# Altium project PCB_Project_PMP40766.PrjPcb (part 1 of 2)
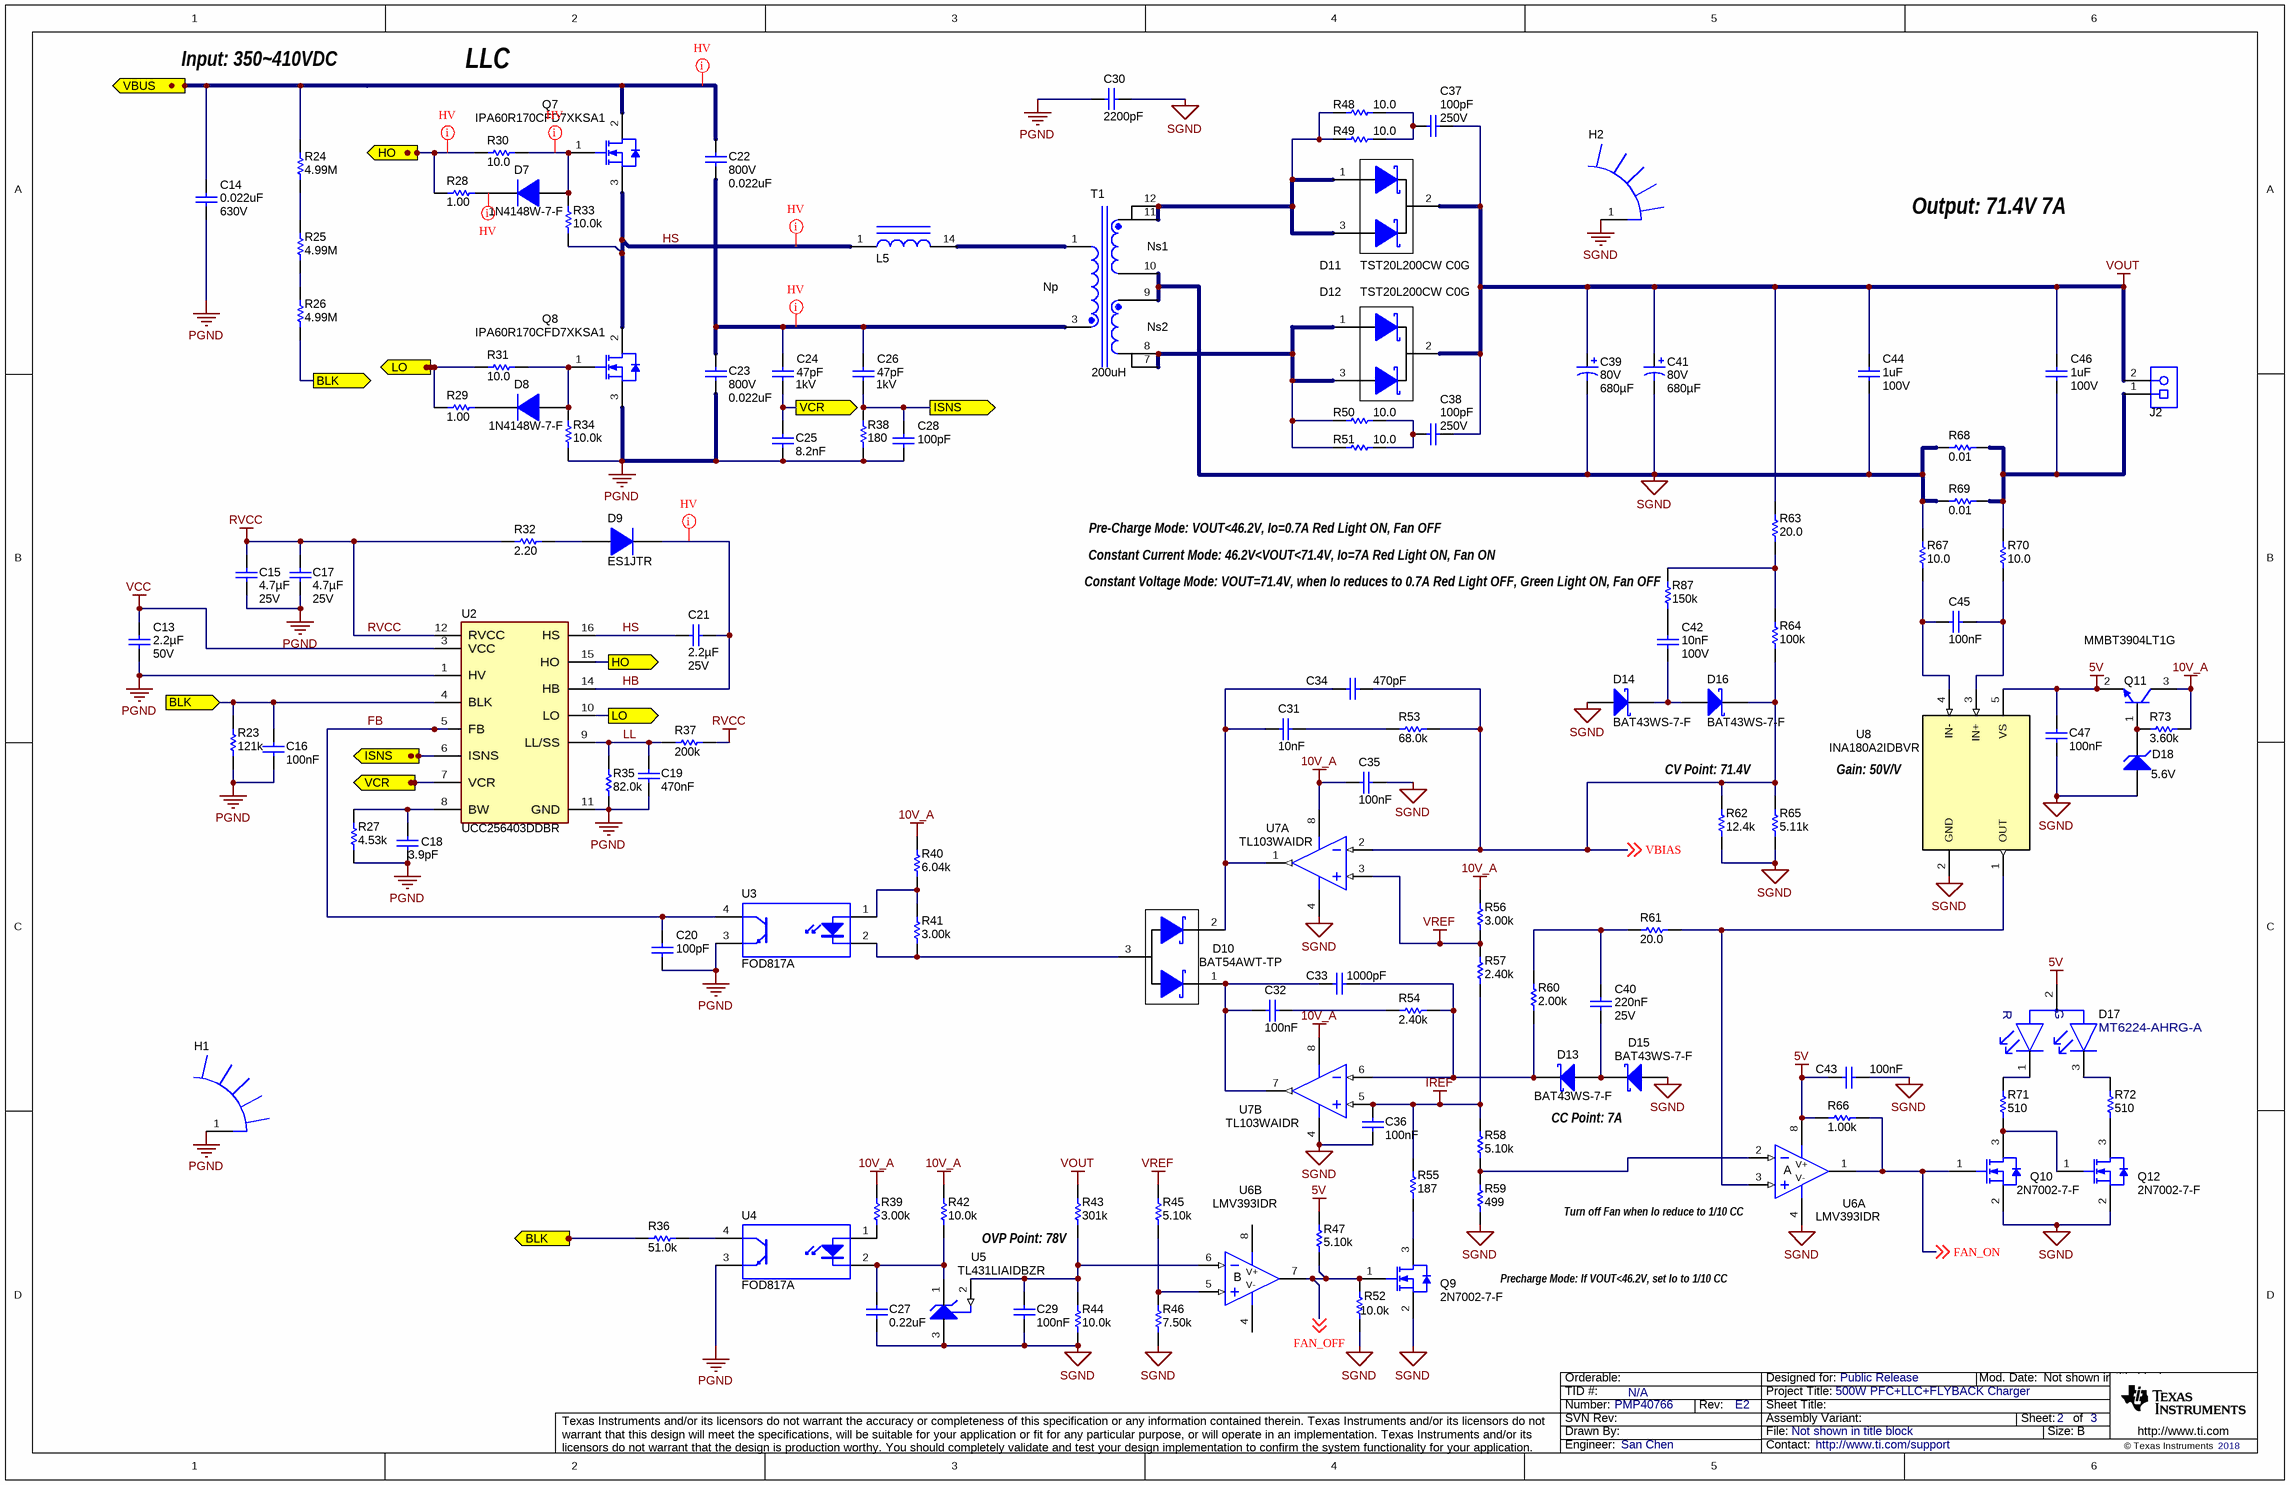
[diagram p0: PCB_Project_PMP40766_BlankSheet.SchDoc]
TID: N/A; TechSupport: http://www.ti.com/support; SCH_Rev: E2; PRJ_Title: 500W PFC+LLC+FLYBACK Charger; PRJ_Number: PMP40766; PRJ_Engineer: San Chen; PRJ_Customer: Public Release; PCB_Rev: E2; PCB_Layout: San Chen; CopyrightYear: 2018
3 sheets, 214 parts. Net scope: flat (ports and power ports of the same name join across sheets).
Board file: PCB_Project_PMP40766_PCB.PcbDoc
Sheets:
  PCB_Project_PMP40766_BlankSheet.SchDoc
  PCB_Project_PMP40766_CoverSheet.SchDoc
  PCB_Project_PMP40766_EVM_Hardware.SchDoc

## Sheet PCB_Project_PMP40766_BlankSheet.SchDoc
size 431 x 279 mm; Date: Not shown in title block; ApprovedBy: Not shown in title block; CheckedBy: Not shown in title block; Author: Not shown in title block; CompanyName: Not shown in title block; Engineer: Not shown in title block; Organization: Not shown in title block; Address1: Not shown in title block; Address2: Not shown in title block; Address3: Not shown in title block; Address4: Not shown in title block; DocumentNumber: 1; Revision: Use project parameter SCH_Rev; SheetNumber: 2; SheetTotal: 3; PageSetup: Record=PageOptions¦CenterHorizontal=True¦CenterVertical=True¦PrintScale=1.00¦XCorrection=1.00¦YCorrection=1.00¦PrintKind=0¦BorderSize=5000000¦LeftOffset=0¦BottomOffset=0¦Orientation=2¦PaperLength=1000¦PaperWidth=1000¦Scale=100¦PaperSource=15¦PrintQuality=600¦MediaType=1¦DitherType=10¦PaperKind=Letter¦PrintScaleMode=1

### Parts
C13  Cap_F: 2.2µF  VDC_V: 50V  [0805_HV]  (hidden comment: C2012X7R1H225K125AC)
C14  VDC_V: 630V  ValueDisplayed: 0.022uF  [ECWF_L_1250x620x1050]  (hidden comment: ECW-F6223HL)
C15  Cap_F: 4.7µF  VDC_V: 25V  [0805_HV]  (hidden comment: C2012X7R1E475K125AB)
C16  Cap_F: 100nF  [0603]  (hidden comment: C0603X104K3RACTU)
C17  Cap_F: 4.7µF  VDC_V: 25V  [0805_HV]  (hidden comment: C2012X7R1E475K125AB)
C18  ValueDisplayed: 3.9pF  [0603]  (hidden comment: 06035A3R9CAT2A)
C19  Cap_F: 470nF  [0603]  (hidden comment: C0603C474K4RACTU)
C20  ValueDisplayed: 100pF  [0603]  (hidden comment: GRM1885C1H101JA01D)
C21  Cap_F: 2.2µF  VDC_V: 25V  [0805_150]  (hidden comment: 08053C225KAT2A)
C22  VDC_V: 800V  ValueDisplayed: 0.022uF  [WCAP-FTX2_1500x700x1250]  (hidden comment: ECW-H8223HA)
C23  VDC_V: 800V  ValueDisplayed: 0.022uF  [WCAP-FTX2_1500x700x1250]  (hidden comment: ECW-H8223HA)
C24  VDC_V: 1kV  ValueDisplayed: 47pF  [1206]  (hidden comment: VJ1206A470JXGAT5Z)
C25  Cap_F: 8.2nF  [0603]  (hidden comment: CL10B822KB8NNNC)
C26  VDC_V: 1kV  ValueDisplayed: 47pF  [1206]  (hidden comment: VJ1206A470JXGAT5Z)
C27  ValueDisplayed: 0.22uF  [0603]  (hidden comment: GRM188R71E224KA88D)
C28  ValueDisplayed: 100pF  [0603]  (hidden comment: GRM1885C1H101JA01D)
C29  Cap_F: 100nF  [0603]  (hidden comment: C0603X104K3RACTU)
C30  ValueDisplayed: 2200pF  [C900_9x13]  (hidden comment: C921U222MVVDBA7317)
C31  Cap_F: 10nF  [0603]  (hidden comment: C0603X103K5RACTU)
C32  Cap_F: 100nF  [0603]  (hidden comment: C0603X104K3RACTU)
C33  ValueDisplayed: 1000pF  [0603]  (hidden comment: C0603C102K3GACTU)
C34  Cap_F: 470pF  [0603]  (hidden comment: C0603X471K5RACTU)
C35  Cap_F: 100nF  [0603]  (hidden comment: C0603X104K3RACTU)
C36  Cap_F: 100nF  [0603]  (hidden comment: C0603X104K3RACTU)
C37  VDC_V: 250V  ValueDisplayed: 100pF  [0805_HV]  (hidden comment: CL21C101JECNNWC)
C38  VDC_V: 250V  ValueDisplayed: 100pF  [0805_HV]  (hidden comment: CL21C101JECNNWC)
C39  VDC_V: 80V  ValueDisplayed: 680µF  [UES_1600x2500]  (hidden comment: EEUFS1K681)
C40  Cap_F: 220nF  VDC_V: 25V  [0603]  (hidden comment: C1608X7R1E224K080AC)
C41  VDC_V: 80V  ValueDisplayed: 680µF  [UES_1600x2500]  (hidden comment: EEUFS1K681)
C42  Cap_F: 10nF  VDC_V: 100V  [0603]  (hidden comment: C0603X103K1RACTU)
C43  Cap_F: 100nF  [0603]  (hidden comment: C0603X104K3RACTU)
C44  VDC_V: 100V  ValueDisplayed: 1uF  [1206_180]  (hidden comment: GRM31CR72A105KA01L)
C45  Cap_F: 100nF  [0603]  (hidden comment: C0603X104K3RACTU)
C46  VDC_V: 100V  ValueDisplayed: 1uF  [1206_180]  (hidden comment: GRM31CR72A105KA01L)
C47  Cap_F: 100nF  [0603]  (hidden comment: C0603X104K3RACTU)
D7  1N4148W-7-F  [SOD-123]
D8  1N4148W-7-F  [SOD-123]
D9  ES1JTR  [SMA]
D10  BAT54AWT-TP  [SOT-323]
D11  TST20L200CW C0G  [TO-220AB]
D12  TST20L200CW C0G  [TO-220AB]
D13  BAT43WS-7-F  [SOD-323]
D14  BAT43WS-7-F  [SOD-323]
D15  BAT43WS-7-F  [SOD-323]
D16  BAT43WS-7-F  [SOD-323]
D17  MT6224-AHRG-A  [FP-MT6224-AHRG-A_RADIAL-MFG]
D18  value 5.6V  [SOD-323]  (hidden comment: MM3Z5V6ST1G)
H1  40mm*120mm  [Heatsink1]  (value not drawn)
H2  (no value)  [Heatsink2]
J2  691216510002S  [Wurth_691216510002]  (value not drawn)
L5  YXS50666T  [PQ2020]  (value not drawn)
Q7  IPA60R170CFD7XKSA1  [TO-220FP]
Q8  IPA60R170CFD7XKSA1  [TO-220FP]
Q9  2N7002-7-F  [SOT-23]
Q10  2N7002-7-F  [SOT-23]
Q11  MMBT3904LT1G  [SOT-23]
Q12  2N7002-7-F  [SOT-23]
R23  ValueDisplayed: 121k  [0603]  (hidden comment: RC0603FR-07121KL)
R24  ValueDisplayed: 4.99M  [1206]  (hidden comment: CRCW12064M99FKEA)
R25  ValueDisplayed: 4.99M  [1206]  (hidden comment: CRCW12064M99FKEA)
R26  ValueDisplayed: 4.99M  [1206]  (hidden comment: CRCW12064M99FKEA)
R27  ValueDisplayed: 4.53k  [0603]  (hidden comment: RC0603FR-074K53L)
R28  ValueDisplayed: 1.00  [1206]  (hidden comment: RC1206FR-071RL)
R29  ValueDisplayed: 1.00  [1206]  (hidden comment: RC1206FR-071RL)
R30  ValueDisplayed: 10.0  [1206]  (hidden comment: RC1206FR-0710RL)
R31  ValueDisplayed: 10.0  [1206]  (hidden comment: RC1206FR-0710RL)
R32  ValueDisplayed: 2.20  [0805_HV]  (hidden comment: RC0805FR-072R2L)
R33  ValueDisplayed: 10.0k  [0603]  (hidden comment: RC0603FR-0710KL)
R34  ValueDisplayed: 10.0k  [0603]  (hidden comment: RC0603FR-0710KL)
R35  ValueDisplayed: 82.0k  [0603]  (hidden comment: RC0603FR-0782KL)
R36  ValueDisplayed: 51.0k  [0603]  (hidden comment: RC0603FR-0751KL)
R37  ValueDisplayed: 200k  [0603]  (hidden comment: RC0603FR-07200KL)
R38  ValueDisplayed: 180  [0603]  (hidden comment: RC0603FR-07180RL)
R39  ValueDisplayed: 3.00k  [0603]  (hidden comment: RC0603FR-073KL)
R40  ValueDisplayed: 6.04k  [0603]  (hidden comment: RC0603FR-076K04L)
R41  ValueDisplayed: 3.00k  [0603]  (hidden comment: RC0603FR-073KL)
R42  ValueDisplayed: 10.0k  [0603]  (hidden comment: RC0603FR-0710KL)
R43  ValueDisplayed: 301k  [0603]  (hidden comment: RC0603FR-07301KL)
R44  ValueDisplayed: 10.0k  [0603]  (hidden comment: RC0603FR-0710KL)
R45  ValueDisplayed: 5.10k  [0603]  (hidden comment: RC0603FR-075K1L)
R46  ValueDisplayed: 7.50k  [0603]  (hidden comment: RC0603FR-077K5L)
R47  ValueDisplayed: 5.10k  [0603]  (hidden comment: RC0603FR-075K1L)
R48  ValueDisplayed: 10.0  [1206]  (hidden comment: RC1206FR-0710RL)
R49  ValueDisplayed: 10.0  [1206]  (hidden comment: RC1206FR-0710RL)
R50  ValueDisplayed: 10.0  [1206]  (hidden comment: RC1206FR-0710RL)
R51  ValueDisplayed: 10.0  [1206]  (hidden comment: RC1206FR-0710RL)
R52  ValueDisplayed: 10.0k  [0603]  (hidden comment: RC0603FR-0710KL)
R53  ValueDisplayed: 68.0k  [0603]  (hidden comment: RC0603FR-0768KL)
R54  ValueDisplayed: 2.40k  [0603]  (hidden comment: RC0603FR-072K4L)
R55  ValueDisplayed: 187  [0603]  (hidden comment: RC0603FR-07187RL)
R56  ValueDisplayed: 3.00k  [0603]  (hidden comment: RC0603FR-073KL)
R57  ValueDisplayed: 2.40k  [0603]  (hidden comment: RC0603FR-072K4L)
R58  ValueDisplayed: 5.10k  [0603]  (hidden comment: RC0603FR-075K1L)
R59  ValueDisplayed: 499  [0603]  (hidden comment: RC0603FR-07499RL)
R60  ValueDisplayed: 2.00k  [0603]  (hidden comment: RC0603FR-072KL)
R61  ValueDisplayed: 20.0  [0603]  (hidden comment: RC0603FR-0720RL)
R62  ValueDisplayed: 12.4k  [0603]  (hidden comment: CRCW060312K4FKEA)
R63  ValueDisplayed: 20.0  [0603]  (hidden comment: RC0603FR-0720RL)
R64  ValueDisplayed: 100k  [0603]  (hidden comment: RC0603FR-07100KL)
R65  ValueDisplayed: 5.11k  [0603]  (hidden comment: RC0603FR-075K11L)
R66  ValueDisplayed: 1.00k  [0603]  (hidden comment: RC0603FR-071KL)
R67  ValueDisplayed: 10.0  [0603]  (hidden comment: RC0603FR-0710RL)
R68  ValueDisplayed: 0.01  [1206]  (hidden comment: CSR1206FK10L0)
R69  ValueDisplayed: 0.01  [1206]  (hidden comment: CSR1206FK10L0)
R70  ValueDisplayed: 10.0  [0603]  (hidden comment: RC0603FR-0710RL)
R71  ValueDisplayed: 510  [0603]  (hidden comment: RC0603FR-07510RL)
R72  ValueDisplayed: 510  [0603]  (hidden comment: RC0603FR-07510RL)
R73  ValueDisplayed: 3.60k  [0603]  (hidden comment: RC0603FR-073K6L)
R87  ValueDisplayed: 150k  [0603]  (hidden comment: RC0603FR-07150KL)
T1  value 200uH  [PQ3230_2]  (hidden comment: YXS61212T)
U2  UCC256403DDBR  [DDB0014A-MFG]
U3  FOD817A  [DIP-4]
U4  FOD817A  [DIP-4]
U5  TL431LIAIDBZR  [DBZ0003A_N]
U6  LMV393IDR  [D0008A_L]  (parts A,B of 2)
U7  TL103WAIDR  [D0008A_L]  (parts A,B of 2)
U8  INA180A2IDBVR  [DBV0005A_N]

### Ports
BLK (in), BLK (out), HO (in), HO (out), ISNS (in), ISNS (out), LO (in), LO (out), VBUS (in), VCR (in), VCR (out)

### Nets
5V: C43.1 C47.1 D17.2(COMMON_ANODE) Q11.2(E) R47.2 R66.1 U6.8(V+) U8.5(VS)
10V_A: C35.1 Q11.3(C) R39.2 R40.2 R42.2 R56.1 R73.1 U7.8(VCC+)
IREF: C36.2 R55.2 R57.1 R58.2 U7.5(IN2+)
PGND: C13.2 C14.2 C15.2 C16.2 C17.2 C18.2 C19.2 C20.2 C23.2 C25.2 C28.2 C30.2 H1.1 Q8.3(S) R23.1 R27.1 R34.1 R35.1 R38.1 U2.1(HV) U2.11(GND) U3.3(E) U4.3(E)
RVCC: C15.1 C17.1 R32.1 R37.1 U2.12(RVCC)
SGND: C27.2 C29.2 C30.1 C35.2 C36.1 C39.2(-) C41.2(-) C43.2 C44.2 C47.2 D14.2(A) D15.2(A) D18.2(A) H2.1 Q9.2(S) Q10.2(S) Q12.2(S) R44.1 R46.1 R52.1 R59.1 R62.1 R65.1 R67.2 R68.1 R69.1 T1.9 T1.10 U5.3(ANODE) U6.4(V-) U7.4(VCC-) U8.2(GND)
VCC: C13.1 U2.3(VCC)
VOUT: C37.1 C38.1 C39.1(+) C41.1(+) C44.1 C46.1 D11.2(K) D12.2(K) J2.2 R43.2 R63.2
VREF: R45.2 R56.2 R57.2 U7.3(IN1+)
BLK: C16.1 R23.2 R26.1 R36.2 U2.4(BLK) ; port BLK
FAN_OFF: Q9.1(G) R47.1 R52.2 U6.7(OUT) ; off-sheet FAN_OFF
FAN_ON: Q10.1(G) R66.2 U6.1(OUT) ; off-sheet FAN_ON
FB: C20.1 U2.5(FB) U3.4(C)
HB: C21.2 D9.1(K) U2.14(HB)
HO: R28.1 R30.1 U2.15(HO) ; port HO
HS: C21.1 L5.1 Q7.3(S) Q8.2(D) R33.1 U2.16(HS)
ISNS: C26.2 C28.1 R38.2 U2.6(ISNS) ; port ISNS
LL: C19.1 R35.2 R37.2 U2.9(LL/SS)
LO: R29.1 R31.1 U2.10(LO) ; port LO
VBIAS: C34.1 D16.1(K) R53.1 R62.2 R64.1 R65.2 U7.2(IN1-) ; off-sheet VBIAS
VBUS: C14.1 C22.1 Q7.2(D) R24.2 ; port VBUS
VCR: C24.2 C25.1 U2.7(VCR) ; port VCR
NetC18_1: C18.1 R27.2 U2.8(BW)
NetC22_2: C22.2 C23.1 C24.1 C26.1 T1.3
NetC27_1: C27.1 R42.1 U4.2(K) U5.1(CATHODE)
NetC29_1: C29.1 R43.1 R44.2 U5.2(REF) U6.6(IN-)
NetC31_1: C31.1 C34.2 D10.2(K) U7.1(OUT1)
NetC31_2: C31.2 R53.2
NetC32_1: C32.1 C33.2 D10.1(A) U7.7(OUT2)
NetC32_2: C32.2 R54.1
NetC33_1: C33.1 D13.1(K) R54.2 R60.1 U7.6(IN2-)
NetC37_2: C37.2 R48.2 R49.2
NetC38_2: C38.2 R50.2 R51.2
NetC40_1: C40.1 R60.2 R61.2
NetC40_2: C40.2 D13.2(A) D15.1(K)
NetC42_1: C42.1 R87.1
NetC42_2: C42.2 D14.1(K) D16.2(A)
NetC45_1: C45.1 R67.1 U8.4(IN-)
NetC45_2: C45.2 R70.1 U8.3(IN+)
NetC46_2: C46.2 J2.1 R68.2 R69.2 R70.2
NetD7_1: D7.1(K) R28.2
NetD7_2: D7.2(A) Q7.1(G) R30.2 R33.2
NetD8_1: D8.1(K) R29.2
NetD8_2: D8.2(A) Q8.1(G) R31.2 R34.2
NetD9_2: D9.2(A) R32.2
NetD10_3: D10.3(A) R41.2 U3.2(K)
NetD11_1: D11.1(A) D11.3(A) R48.1 R49.1 T1.11 T1.12
NetD12_1: D12.1(A) D12.3(A) R50.1 R51.1 T1.7 T1.8
NetD17_1: D17.1(RED_CATHODE) R71.2
NetD17_3: D17.3(GREEN_CATHODE) R72.2
NetD18_1: D18.1(K) Q11.1(B) R73.2
NetL5_14: L5.14 T1.1
NetQ9_3: Q9.3(D) R55.1
NetQ10_3: Q10.3(D) Q12.1(G) R71.1
NetQ12_3: Q12.3(D) R72.1
NetR24_1: R24.1 R25.2
NetR25_1: R25.1 R26.2
NetR36_1: R36.1 U4.4(C)
NetR39_1: R39.1 U4.1(A)
NetR40_1: R40.1 R41.1 U3.1(A)
NetR45_1: R45.1 R46.2 U6.5(IN+)
NetR58_1: R58.1 R59.2 U6.2(IN-)
NetR61_1: R61.1 U6.3(IN+) U8.1(OUT)
NetR63_1: R63.1 R64.2 R87.2

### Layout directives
net class HV: HB, HO, HS, NetC22_2, NetD7_1, NetD7_2, VBUS

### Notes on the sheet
- Input: 350~410VDC
- LLC
- Output: 71.4V 7A
- (near T1) Np
- (near T1) Ns1
- (near T1) Ns2
- Pre-Charge Mode: VOUT<46.2V, Io=0.7A Red Light ON, Fan OFF
- Constant Current Mode: 46.2V<VOUT<71.4V, Io=7A Red Light ON, Fan ON
- (near R87) Constant Voltage Mode: VOUT=71.4V, when Io reduces to 0.7A Red Light OFF, Green Light ON, Fan OFF
- CV Point: 71.4V
- Gain: 50V/V
- CC Point: 7A
- (near R43) OVP Point: 78V
- (near U6) Turn off Fan when Io reduce to 1/10 CC
- Precharge Mode: If VOUT<46.2V, set Io to 1/10 CC

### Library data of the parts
C13 = CMP-0007877-2: CAP, CERM, 2.2 uF, 50 V, +/- 10%, X7R, 0805; Manufacturer: TDK; TaMin_C: -55°C; ESR_ohm: 3.66m; Polarized: N; SizeAreaWB_mm2: 6.75; Value1: 0.00366 ohm; U/M: EA; Value: 2.2uF; TaMax_C: 125°C; SizeZ_mm: 1.45; SizeX_mm: 2; SizeY_mm: 1.25; Cap_Case: 0805; SizeArea_mm2: 2.5; IRMS_A: 3.41207A; AEC Category: Q200
C14 = CMP-0012506-3: CAP, Film, 0.022 uF, 630 V, +/- 3%, TH; Manufacturer: Panasonic; TaMin_C: -40°C; Polarized: N; Value1: Unknown; TaMax_C: 105°C; Cap_Case: 12.5x6.2x10.5mm; Cap_F: 22nF; AEC Category: Q200
C15 C17 = CMP-0007870-2: CAP, CERM, 4.7 uF, 25 V, +/- 10%, X7R, 0805; Manufacturer: TDK; TaMin_C: -55°C; Polarized: N; SizeAreaWB_mm2: 6.75; Value1: Unknown; U/M: EA; Value: 4.7uF; TaMax_C: 125°C; SizeZ_mm: 1.45; SizeX_mm: 2; SizeY_mm: 1.25; Cap_Case: 0805; SizeArea_mm2: 2.5; AEC Category: Q200
C16 C29 C32 C35 C36 C43 C45 C47 = CMP-0006979-5: CAP, CERM, 0.1 uF, 25 V, +/- 10%, X7R, 0603; Manufacturer: Kemet; TaMin_C: -55°C; Polarized: N; SizeAreaWB_mm2: 4.68; Value1: Unknown; U/M: EA; Value: 0.1uF; TaMax_C: 125°C; SizeZ_mm: 1; SizeX_mm: 1.6; SizeY_mm: 0.8; Value2: 25V; SizeArea_mm2: 1.28; CompType: Capacitor; AEC Category: Q200
C18 = CMP-0006788-4: CAP, CERM, 3.9 pF, 50 V, +/- 6%, C0G/NP0, 0603; Manufacturer: AVX; TaMin_C: -55°C; ESR_ohm: 7.12d; Polarized: N; SizeAreaWB_mm2: 4.68; Value1: 0.712 ohm; U/M: EA; Value: 3.9pF; TaMax_C: 125°C; SizeZ_mm: 1; SizeX_mm: 1.6; SizeY_mm: 0.8; Value2: 50V; SizeArea_mm2: 1.28; CompType: Capacitor; AEC Category: Q200
C19 = CMP-0006944-4: CAP, CERM, 0.47 uF, 16 V, +/- 10%, X7R, 0603; Manufacturer: Kemet; TaMin_C: -55°C; Polarized: N; SizeAreaWB_mm2: 4.68; Value1: Unknown; U/M: EA; Value: 0.47uF; TaMax_C: 125°C; SizeZ_mm: 1; SizeX_mm: 1.6; SizeY_mm: 0.8; Value2: 16V; SizeArea_mm2: 1.28; CompType: Capacitor; AEC Category: Q200
C20 C28 = CMP-0007171-4: CAP, CERM, 100 pF, 50 V, +/- 5%, C0G/NP0, 0603; Manufacturer: MuRata; TaMin_C: -55°C; Polarized: N; SizeAreaWB_mm2: 4.68; Value1: Unknown; U/M: EA; Value: 100pF; TaMax_C: 125°C; SizeZ_mm: 1; SizeX_mm: 1.6; SizeY_mm: 0.8; Value2: 50V; SizeArea_mm2: 1.28; CompType: Capacitor; AEC Category: Q200
C21 = CMP-0007573-2: CAP, CERM, 2.2 uF, 25 V, +/- 10%, X7R, 0805; Manufacturer: AVX; TaMin_C: -55°C; Polarized: N; SizeAreaWB_mm2: 6.75; Value1: Unknown; U/M: EA; Value: 2.2uF; TaMax_C: 125°C; SizeZ_mm: 1.5; SizeX_mm: 2; SizeY_mm: 1.25; Cap_Case: 0805; SizeArea_mm2: 2.5; CompType: Capacitor; AEC Category: Q200
C22 C23 = CMP-0012312-3: CAP, Film, 0.022 uF, 800 V, +/- 3%, TH; Manufacturer: Panasonic Electronic Components; TaMin_C: -40°C; Polarized: N; SizeAreaWB_mm2: 153; Value1: Unknown; TaMax_C: 105°C; Tolerance_%: 10%; SizeZ_mm: 13; SizeX_mm: 15; SizeY_mm: 7; Cap_Case: 15x7x12.5; SizeArea_mm2: 105; CompType: Capacitor; Cap_F: 220nF; AEC Category: Q200
C24 C26 = CMP-0009034-2: CAP, CERM, 47 pF, 1000 V, +/- 5%, C0G/NP0, 1206; Manufacturer: Vishay-Vitramon; TaMin_C: -55°C; Polarized: N; SizeAreaWB_mm2: 10.92; Value1: Unknown; U/M: EA; Value: 47pF; TaMax_C: 125°C; SizeZ_mm: 1.35; SizeX_mm: 3.2; SizeY_mm: 1.6; Value2: 1000V; SizeArea_mm2: 5.12; AEC Category: Q200
C25 = CMP-0860998-1: CAP, CERM, 8200 pF, 50 V,+/- 10%, X7R, 0603; Manufacturer: Samsung Electro-Mechanics; Value2: 50V; SizeArea_mm2: 1.28; TaMax_C: 125°C; AEC Qualified: N; AEC Category: Q200; SizeAreaWB_mm2: 4.68; ValueDisplayed: 8200pF; SizeY_mm: 0.8; SizeX_mm: 1.6; SizeZ_mm: 1; Value: 8200pF; TaMin_C: -55°C; U/M: EA; CompType: Capacitor
C27 = CMP-0007415-4: CAP, CERM, 0.22 uF, 25 V, +/- 10%, X7R, 0603; Manufacturer: MuRata; TaMin_C: -55°C; Polarized: N; SizeAreaWB_mm2: 4.68; Value1: Unknown; U/M: EA; Value: 0.22uF; TaMax_C: 125°C; SizeZ_mm: 1; SizeX_mm: 1.6; SizeY_mm: 0.8; Value2: 25V; SizeArea_mm2: 1.28; CompType: Capacitor; Cap_F: 220nF; AEC Category: Q200
C30 = CMP-0078358-1: CAP, CERM, 2200 pF, X1 400 VAC/Y1 400 VAC, +/- 20%, Y5V, D9xL13mm; Manufacturer: Kemet; Cap_F: 2.2nF; SizeAreaWB_mm2: 121; VAC_X: 400V; SizeArea_mm2: 81; AEC Qualified: N; AEC Category: Q200; Value: 2200pF; TaMax_C: 125°C; SizeZ_mm: 13; TaMin_C: -40°C; SizeY_mm: 9; U/M: EA; AC_Safety: X1Y1; Cap_Case: 9x13mm
C31 = CMP-0006978-4: CAP, CERM, 0.01 uF, 50 V, +/- 10%, X7R, 0603; Manufacturer: Kemet; TaMin_C: -55°C; Polarized: N; SizeAreaWB_mm2: 4.68; Value1: Unknown; U/M: EA; Value: 0.01uF; TaMax_C: 125°C; SizeZ_mm: 1; SizeX_mm: 1.6; SizeY_mm: 0.8; Value2: 50V; SizeArea_mm2: 1.28; CompType: Capacitor; AEC Category: Q200
C33 = CMP-0006846-4: CAP, CERM, 1000 pF, 25 V, +/- 10%, C0G/NP0, 0603; Manufacturer: Kemet; TaMin_C: -55°C; ESR_ohm: 0; Polarized: N; SizeAreaWB_mm2: 4.68; Value1: 0 ohm; U/M: EA; Value: 1000pF; TaMax_C: 125°C; SizeZ_mm: 1; SizeX_mm: 1.6; SizeY_mm: 0.8; Value2: 25V; SizeArea_mm2: 1.28; CompType: Capacitor; Cap_F: 1nF; IRMS_A: 0A; AEC Category: Q200
C34 = CMP-0006986-4: CAP, CERM, 470 pF, 50 V, +/- 10%, X7R, 0603; Manufacturer: Kemet; TaMin_C: -55°C; SizeAreaWB_mm2: 4.68; Value1: Unknown; U/M: EA; Value: 470pF; TaMax_C: 125°C; SizeZ_mm: 1; SizeX_mm: 1.6; SizeY_mm: 0.8; Value2: 50V; SizeArea_mm2: 1.28; CompType: Capacitor; AEC Category: Q200; Polarized: N
C37 C38 = CMP-0074690-1: CAP, CERM, 100 pF, 250 V,+/- 5%, C0G/NP0, 0805; Manufacturer: Samsung Electro-Mechanics; TaMin_C: -55°C; Polarized: N; SizeAreaWB_mm2: 6.75; U/M: EA; Value: 100pF; TaMax_C: 125°C; SizeZ_mm: 1.45; SizeX_mm: 2.0; SizeY_mm: 1.25; Cap_Case: 0805; SizeArea_mm2: 2.5; AEC Category: Q200
C39 C41 = CMP-0077674-1: CAP, AL, 680 µF, 80 V, +/- 20%, TH; Manufacturer: Panasonic Electronic Components; SizeAreaWB_mm2: 324.0; SizeArea_mm2: 256.0; AEC Qualified: N; AEC Category: Q200; Value: 680uF; TaMax_C: 105°C; SizeZ_mm: 26.5; Polarized: Y; TaMin_C: -40°C; SizeY_mm: 16.0; U/M: EA; CompType: Capacitor; Cap_Case: 16x25mm
C40 = CMP-0007042-4: CAP, CERM, 0.22 uF, 25 V, +/- 10%, X7R, 0603; Manufacturer: TDK; TaMin_C: -55°C; Polarized: N; SizeAreaWB_mm2: 4.68; Value1: Unknown; U/M: EA; Value: 0.22uF; TaMax_C: 125°C; SizeZ_mm: 1; SizeX_mm: 1.6; SizeY_mm: 0.8; SizeArea_mm2: 1.28; AEC Category: Q200
C42 = CMP-0006977-4: CAP, CERM, 0.01 uF, 100 V, +/- 10%, X7R, 0603; Manufacturer: Kemet; TaMin_C: -55°C; Polarized: N; SizeAreaWB_mm2: 4.68; Value1: Unknown; U/M: EA; Value: 0.01uF; TaMax_C: 125°C; SizeZ_mm: 1; SizeX_mm: 1.6; SizeY_mm: 0.8; SizeArea_mm2: 1.28; AEC Category: Q200
C44 C46 = CMP-0008970-2: CAP, CERM, 1 uF, 100 V, +/- 10%, X7R, 1206; Manufacturer: MuRata; TaMin_C: -55°C; Polarized: N; SizeAreaWB_mm2: 10.92; Value1: Unknown; U/M: EA; Value: 1uF; TaMax_C: 125°C; SizeZ_mm: 1.8; SizeX_mm: 3.2; SizeY_mm: 1.6; Cap_Case: 2220; SizeArea_mm2: 5.12; Cap_F: 1µF; AEC Category: Q200
D7 D8 = CMP-0029001-2: Diode, Ultrafast, 100 V, 0.15 A, SOD-123; Manufacturer: Diodes Inc.; SizeX_mm: 3.85; Value2: 1.25V; Green_REACh: Passed; TJmax_C: 150°C; AEC Category: Q101; SizeAreaWB_mm2: 13.095; Value: 100V; Green_Lifecycle: Active; SizeY_mm: 1.7; Value1: 0.15A; SizeArea_mm2: 6.545; Io_A: 1.5dA; SizeZ_mm: 1.35
D9 = CMP-0067545-2: Diode, Superfast Rectifier, 600 V, 1 A, SMA; Manufacturer: SMC Diode Solutions; SizeZ_mm: 2.87; Io_A: 1A; SizeY_mm: 2.92; SizeAreaWB_mm2: 37.3428; Value: 600V; SizeX_mm: 5.59; SizeArea_mm2: 16.3228; Value2: 1.7V; AEC Qualified: N; TJmax_C: 150°C; AEC Category: Q101; RJC_CperW: 35.0
D10 = CMP-0028627-2: Diode, Schottky, 30 V, 0.2 A, SOT-323; Manufacturer: Micro Commercial Components; SizeArea_mm2: 4.84; Io_A: 2dA; Value2: 1V; Value1: 0.2A; TJmax_C: 125°C; SizeY_mm: 2.2; AEC Category: Q101; SizeZ_mm: 1.1; Green_REACh: Incomplete; Value: 30V; Green_Lifecycle: Not Set; SizeAreaWB_mm2: 10.24
D11 D12 = CMP-0028764-3: Diode, Schottky, 200 V, 20 A, TH; Manufacturer: Taiwan Semiconductor Corporation; RJC_CperW: 2; SizeArea_mm2: 45.9; Value1: 20A; Value2: 0.99V; Value: 200V; AEC Qualified: N; SizeY_mm: 4.5; AEC Category: Q101; SizeAreaWB_mm2: 79.3; Green_Lifecycle: Not Set; Green_REACh: Incomplete; Vf_V: 9.9dV; TJmax_C: 150°C; SizeX_mm: 10.2; SizeZ_mm: 19.4
D13-D16 = CMP-0028449-2: Diode, Schottky, 30 V, 0.2 A, SOD-323; Manufacturer: Diodes Inc.; SizeZ_mm: 1; Value1: 0.2A; SizeArea_mm2: 3.645; Io_A: 2dA; Value: 30V; SizeAreaWB_mm2: 8.695; SizeY_mm: 1.35; AEC Category: Q101; Vf_V: 1V; Green_REACh: Incomplete; SizeX_mm: 2.7; Green_Lifecycle: Not Set
D17 = CMP-0087778-1: LED GRN/RED DIFF 5MM ROUND T/H; Manufacturer: Marktech Optoelectronics; Color: Green, Red; LambdaP: 568/630nm; Angle: 70°; Vr_V: 5V; LambdaD: 570/622nm
D18 = CMP-0085741-1: Diode, Zener, 5.6 V, 300 mW, SOD-323; Manufacturer: ON Semiconductor; AEC Category: Q101; SizeZ_mm: 1; SizeArea_mm2: 3.645; AEC Qualified: N; Value1: 0.3W; Power_W: 300mW; SizeX_mm: 2.7; SizeAreaWB_mm2: 8.695; RJA_CperW: 416; SizeY_mm: 1.35
H1 = 7106DG: CompType: Heatsink
H2 = 7106DG: PartNumber: 40mm*40mm; CompType: Heatsink
J2 = CMP-0054770-2: Receptacle, 5.08mm, 2x1, Brass, TH; Manufacturer: Wurth Elektronik; Pitch_mm: 5.08; CNHeader: FALSE; Gender: Female; Row_Count: 1; Cert_UL: Y; Current_A: 10A; Voltage_V: 300V
L5 = LLC Inductor: Transformer, 58uH, TH; Manufacturer: YAXIN ELECTRONICS; SymbolCreator: Altium; ValueDisplayed: 58µH; DCR_ohm: 0.052; Lp: 58; Ind_H: 0.000058; SizeX_mm: 22; SizeY_mm: 26.5; SizeZ_mm: 10.5
Q7 Q8 = CMP-0079306-2: MOSFET, N-CH, 600 V, 8 A, TO-220FP; Alternate Manufacturer: None; Manufacturer: Infineon Technologies; SizeArea_mm2: 45.9; Vgs_V: 20V; Value2: 28 nC; QgTyp_nC: 28; AEC Qualified: N; SizeX_mm: 10.2; Value: 600V; Value1: ? ohm; AEC Category: Q101; ChMode: Enhancement; SizeZ_mm: 20; IdsMax_A: 8A; SizeAreaWB_mm2: 79.3; SizeY_mm: 4.5
Q9 Q10 Q12 = CMP-0000769-1: MOSFET, N-CH, 60 V, 0.17 A, SOT-23; Alternate Manufacturer: None; Manufacturer: Diodes Inc.; SizeZ_mm: 1.1; ChType: N; Value2: 223 nC; Value1: 7; VdsMax_V: 60V; SizeX_mm: 2.5; SizeY_mm: 3; Vgs_V: 20V; Value: 60V; Rdson45_ohm: 7.5; AEC Category: Q101; IdsMax_A: 1.7dA; SizeAreaWB_mm2: 14; U/M: EA; QgTyp_nC: 223
Q11 = CMP-0000419-2: Transistor, NPN, 40 V, 0.2 A, SOT-23; Manufacturer: ON Semiconductor; TaMax_C: 150°C; Value2: 300; Value1: 0.2 A; Vcesat1_V: 3dV; SizeX_mm: 2.5; SizeY_mm: 3; TaMin_C: -55°C; IcRated_A: 2dA; CompType: BJT; SizeZ_mm: 1.1; Value: 40 V; SizeArea_mm2: 7.5; NPN: 1; Vceo_V: 40V; PNP: 0; AEC Category: Q101; SizeAreaWB_mm2: 14; U/M: EA
R23 = CMP-0022770-4: RES, 121 k, 1%, 0.1 W, 0603; Manufacturer: Yageo; Power_W: 100mW; TempCo: 100 ppm/C; Value: 121k; EIA_Code: E96; SizeX_mm: 1.6; SizeY_mm: 0.8; SizeZ_mm: 1; Value2: 0.1W; SizeArea_mm2: 1.28; AEC Qualified: N; VDC_V: 75V; AEC Category: Q200; SizeAreaWB_mm2: 4.68
R24-R26 = CMP-0017039-3: RES, 4.99 M, 1%, 0.25 W, AEC-Q200 Grade 0, 1206; Manufacturer: Vishay-Dale; Power_W: 250mW; TempCo: 100 ppm/C; Value_Code: 4M99; Value: 4.99Meg; EIA_Code: E96; SizeX_mm: 3.2; SizeY_mm: 1.6; SizeZ_mm: 1.35; Value2: 0.25W; SizeArea_mm2: 5.12; AEC Qualified: Y; VDC_V: 200V; AEC Category: Q200; AEC Grade: 0
R27 = CMP-0023150-5: RES, 4.53 k, 1%, 0.1 W, 0603; Manufacturer: Yageo; Power_W: 100mW; TempCo: 100 ppm/C; Value_Code: 4k53; Value: 4.53k; EIA_Code: E96; SizeX_mm: 1.6; SizeY_mm: 0.8; SizeZ_mm: 1; Value2: 0.1W; SizeArea_mm2: 1.28; AEC Qualified: N; VDC_V: 75V; AEC Category: Q200; SizeAreaWB_mm2: 4.68
R28 R29 = CMP-0018059-2: RES, 1.00, 1%, 0.25 W, 1206; Manufacturer: Yageo America; Power_W: 250mW; TempCo: 200 ppm/C; Value_Code: 1R00; U/M: EA; Value: 1.00; EIA_Code: E96; Res_ohm: 1; SizeX_mm: 3.2; SizeY_mm: 1.6; SizeZ_mm: 1.35; Value2: 0.25W; SizeArea_mm2: 5.12; VDC_V: 200V; AEC Category: Q200
R30 R31 R48-R51 = CMP-0017851-2: RES, 10.0, 1%, 0.25 W, 1206; Manufacturer: Yageo America; Power_W: 250mW; TempCo: 200 ppm/C; Value_Code: 10R0; U/M: EA; Value: 10.0; EIA_Code: E96; Res_ohm: 10; SizeX_mm: 3.2; SizeY_mm: 1.6; SizeZ_mm: 1.35; Value2: 0.25W; SizeArea_mm2: 5.12; VDC_V: 200V; AEC Category: Q200
R32 = CMP-0021901-2: RES, 2.20, 1%, 0.125 W, 0805; Manufacturer: Yageo America; Power_W: 125mW; TempCo: 200 ppm/C; Value_Code: 2R20; U/M: EA; Value: 2.20; Res_ohm: 2.2; SizeX_mm: 2; SizeY_mm: 1.25; SizeZ_mm: 1.45; Value2: 0.125W; SizeArea_mm2: 2.5; VDC_V: 150V; AEC Category: Q200
R33 R34 R42 R44 R52 = CMP-0022746-5: RES, 10.0 k, 1%, 0.1 W, 0603; Manufacturer: Yageo; Power_W: 100mW; TempCo: 100 ppm/C; Value_Code: 10k0; Value: 10.0k; EIA_Code: E96; Res_ohm: 10k; SizeX_mm: 1.6; SizeY_mm: 0.8; SizeZ_mm: 1; Value2: 0.1W; SizeArea_mm2: 1.28; AEC Qualified: N; VDC_V: 75V; AEC Category: Q200; SizeAreaWB_mm2: 4.68
R35 = CMP-0023292-5: RES, 82.0 k, 1%, 0.1 W, 0603; Manufacturer: Yageo; Power_W: 100mW; TempCo: 100 ppm/C; Value_Code: 82k0; Value: 82.0k; Res_ohm: 82k; SizeX_mm: 1.6; SizeY_mm: 0.8; SizeZ_mm: 1; Value2: 0.1W; SizeArea_mm2: 1.28; AEC Qualified: N; VDC_V: 75V; AEC Category: Q200; SizeAreaWB_mm2: 4.68
R36 = CMP-0023167-5: RES, 51.0 k, 1%, 0.1 W, 0603; Manufacturer: Yageo; Power_W: 100mW; TempCo: 100 ppm/C; Value_Code: 51k0; Value: 51.0k; Res_ohm: 51k; SizeX_mm: 1.6; SizeY_mm: 0.8; SizeZ_mm: 1; Value2: 0.1W; SizeArea_mm2: 1.28; AEC Qualified: N; VDC_V: 75V; AEC Category: Q200; SizeAreaWB_mm2: 4.68
R37 = CMP-0022901-4: RES, 200 k, 1%, 0.1 W, 0603; Manufacturer: Yageo; Power_W: 100mW; TempCo: 100 ppm/C; Value: 200k; EIA_Code: E96; SizeX_mm: 1.6; SizeY_mm: 0.8; SizeZ_mm: 1; Value2: 0.1W; AEC Qualified: N; VDC_V: 75V; AEC Category: Q200; SizeArea_mm2: 1.28; SizeAreaWB_mm2: 4.68
R38 = CMP-0022845-5: RES, 180, 1%, 0.1 W, 0603; Manufacturer: Yageo; Power_W: 100mW; TempCo: 100 ppm/C; Value_Code: 180R; Value: 180; SizeX_mm: 1.6; SizeY_mm: 0.8; SizeZ_mm: 1; Value2: 0.1W; SizeArea_mm2: 1.28; AEC Qualified: N; VDC_V: 75V; AEC Category: Q200; SizeAreaWB_mm2: 4.68
R39 R41 R56 = CMP-0023091-5: RES, 3.00 k, 1%, 0.1 W, 0603; Manufacturer: Yageo; Power_W: 100mW; TempCo: 100 ppm/C; Value_Code: 3k00; Value: 3.00k; Res_ohm: 3k; SizeX_mm: 1.6; SizeY_mm: 0.8; SizeZ_mm: 1; Value2: 0.1W; SizeArea_mm2: 1.28; AEC Qualified: N; VDC_V: 75V; AEC Category: Q200; SizeAreaWB_mm2: 4.68
R40 = CMP-0023246-5: RES, 6.04 k, 1%, 0.1 W, 0603; Manufacturer: Yageo; Power_W: 100mW; TempCo: 100 ppm/C; Value_Code: 6k04; Value: 6.04k; EIA_Code: E96; SizeX_mm: 1.6; SizeY_mm: 0.8; SizeZ_mm: 1; Value2: 0.1W; SizeArea_mm2: 1.28; AEC Qualified: N; VDC_V: 75V; AEC Category: Q200; SizeAreaWB_mm2: 4.68
R43 = CMP-0023014-4: RES, 301 k, 1%, 0.1 W, 0603; Manufacturer: Yageo; Power_W: 100mW; TempCo: 100 ppm/C; Value: 301k; EIA_Code: E96; SizeX_mm: 1.6; SizeY_mm: 0.8; SizeZ_mm: 1; Value2: 0.1W; SizeArea_mm2: 1.28; AEC Qualified: N; VDC_V: 75V; AEC Category: Q200; SizeAreaWB_mm2: 4.68
R45 R47 R58 = CMP-0023198-5: RES, 5.10 k, 1%, 0.1 W, 0603; Manufacturer: Yageo; Power_W: 100mW; TempCo: 100 ppm/C; Value_Code: 5k10; Value: 5.10k; Res_ohm: 5.1k; SizeX_mm: 1.6; SizeY_mm: 0.8; SizeZ_mm: 1; Value2: 0.1W; SizeArea_mm2: 1.28; AEC Qualified: N; VDC_V: 75V; AEC Category: Q200; SizeAreaWB_mm2: 4.68
R46 = CMP-0023279-5: RES, 7.50 k, 1%, 0.1 W, 0603; Manufacturer: Yageo; Power_W: 100mW; TempCo: 100 ppm/C; Value_Code: 7k50; Value: 7.50k; EIA_Code: E96; Res_ohm: 7.5k; SizeX_mm: 1.6; SizeY_mm: 0.8; SizeZ_mm: 1; Value2: 0.1W; SizeArea_mm2: 1.28; AEC Qualified: N; VDC_V: 75V; AEC Category: Q200; SizeAreaWB_mm2: 4.68
R53 = CMP-0023239-5: RES, 68.0 k, 1%, 0.1 W, 0603; Manufacturer: Yageo; Power_W: 100mW; TempCo: 100 ppm/C; Value_Code: 68k0; Value: 68.0k; Res_ohm: 68k; SizeX_mm: 1.6; SizeY_mm: 0.8; SizeZ_mm: 1; Value2: 0.1W; SizeArea_mm2: 1.28; AEC Qualified: N; VDC_V: 75V; AEC Category: Q200; SizeAreaWB_mm2: 4.68
R54 R57 = CMP-0022991-5: RES, 2.40 k, 1%, 0.1 W, 0603; Manufacturer: Yageo; Power_W: 100mW; TempCo: 100 ppm/C; Value_Code: 2k40; Value: 2.40k; Res_ohm: 2.4k; SizeX_mm: 1.6; SizeY_mm: 0.8; SizeZ_mm: 1; Value2: 0.1W; SizeArea_mm2: 1.28; AEC Qualified: N; VDC_V: 75V; AEC Category: Q200; SizeAreaWB_mm2: 4.68
R55 = CMP-0022849-5: RES, 187, 1%, 0.1 W, 0603; Manufacturer: Yageo; Power_W: 100mW; TempCo: 100 ppm/C; Value_Code: 187R; Value: 187; EIA_Code: E96; SizeX_mm: 1.6; SizeY_mm: 0.8; SizeZ_mm: 1; Value2: 0.1W; SizeArea_mm2: 1.28; AEC Qualified: N; VDC_V: 75V; AEC Category: Q200; SizeAreaWB_mm2: 4.68
R59 = CMP-0023141-5: RES, 499, 1%, 0.1 W, 0603; Manufacturer: Yageo; Power_W: 100mW; TempCo: 100 ppm/C; Value_Code: 499R; Value: 499; EIA_Code: E96; SizeX_mm: 1.6; SizeY_mm: 0.8; SizeZ_mm: 1; Value2: 0.1W; SizeArea_mm2: 1.28; AEC Qualified: N; VDC_V: 75V; AEC Category: Q200; SizeAreaWB_mm2: 4.68
R60 = CMP-0023000-5: RES, 2.00 k, 1%, 0.1 W, 0603; Manufacturer: Yageo; Power_W: 100mW; TempCo: 100 ppm/C; Value_Code: 2k00; Value: 2.00k; EIA_Code: E96; Res_ohm: 2k; SizeX_mm: 1.6; SizeY_mm: 0.8; SizeZ_mm: 1; Value2: 0.1W; SizeArea_mm2: 1.28; AEC Qualified: N; VDC_V: 75V; AEC Category: Q200; SizeAreaWB_mm2: 4.68
R61 R63 = CMP-0022908-4: RES, 20.0, 1%, 0.1 W, 0603; Manufacturer: Yageo; Power_W: 100mW; TempCo: 100 ppm/C; Value_Code: 20R0; Value: 20.0; EIA_Code: E96; Res_ohm: 20; SizeX_mm: 1.6; SizeY_mm: 0.8; SizeZ_mm: 1; Value2: 0.1W; SizeArea_mm2: 1.28; AEC Qualified: N; VDC_V: 75V; AEC Category: Q200; SizeAreaWB_mm2: 4.68
R62 = CMP-0022031-4: RES, 12.4 k, 1%, 0.1 W, AEC-Q200 Grade 0, 0603; Manufacturer: Vishay-Dale; Power_W: 100mW; TempCo: 100 ppm/C; Value_Code: 12k4; Value: 12.4k; EIA_Code: E96; SizeX_mm: 1.6; SizeY_mm: 0.8; SizeZ_mm: 1; Value2: 0.1W; SizeArea_mm2: 1.28; AEC Qualified: Y; VDC_V: 75V; AEC Category: Q200; AEC Grade: 0
R64 = CMP-0022735-5: RES, 100 k, 1%, 0.1 W, 0603; Manufacturer: Yageo; Power_W: 100mW; TempCo: 100 ppm/C; Value: 100k; EIA_Code: E96; SizeX_mm: 1.6; SizeY_mm: 0.8; SizeZ_mm: 1; Value2: 0.1W; SizeArea_mm2: 1.28; AEC Qualified: N; VDC_V: 75V; AEC Category: Q200; SizeAreaWB_mm2: 4.68
R65 = CMP-0023197-5: RES, 5.11 k, 1%, 0.1 W, 0603; Manufacturer: Yageo; Power_W: 100mW; TempCo: 100 ppm/C; Value_Code: 5k11; Value: 5.11k; EIA_Code: E96; SizeX_mm: 1.6; SizeY_mm: 0.8; SizeZ_mm: 1; Value2: 0.1W; SizeArea_mm2: 1.28; AEC Qualified: N; VDC_V: 75V; AEC Category: Q200; SizeAreaWB_mm2: 4.68
R66 = CMP-0022895-5: RES, 1.00 k, 1%, 0.1 W, 0603; Manufacturer: Yageo; Power_W: 100mW; TempCo: 100 ppm/C; Value_Code: 1k00; Value: 1.00k; EIA_Code: E96; Res_ohm: 1k; SizeX_mm: 1.6; SizeY_mm: 0.8; SizeZ_mm: 1; Value2: 0.1W; SizeArea_mm2: 1.28; AEC Qualified: N; VDC_V: 75V; AEC Category: Q200; SizeAreaWB_mm2: 4.68
R67 R70 = CMP-0022751-4: RES, 10.0, 1%, 0.1 W, 0603; Manufacturer: Yageo; Power_W: 100mW; TempCo: 100 ppm/C; Value_Code: 10R0; Value: 10.0; EIA_Code: E96; Res_ohm: 10; SizeX_mm: 1.6; SizeY_mm: 0.8; SizeZ_mm: 1; Value2: 0.1W; SizeArea_mm2: 1.28; AEC Qualified: N; VDC_V: 75V; AEC Category: Q200; SizeAreaWB_mm2: 4.68
R68 R69 = CMP-0017256-2: RES, 0.01, 1%, 0.5 W, 1206; Manufacturer: Stackpole Electronics Inc; Power_W: 500mW; TempCo: 100 ppm/C; Value_Code: R010; U/M: EA; Value: 0.01; EIA_Code: E96; SizeX_mm: 3.2; SizeY_mm: 1.6; SizeZ_mm: 1.35; Value2: 0.5W; SizeArea_mm2: 5.12; AEC Category: Q200
R71 R72 = CMP-0023163-5: RES, 510, 1%, 0.1 W, 0603; Manufacturer: Yageo; Power_W: 100mW; TempCo: 100 ppm/C; Value_Code: 510R; Value: 510; SizeX_mm: 1.6; SizeY_mm: 0.8; SizeZ_mm: 1; Value2: 0.1W; SizeArea_mm2: 1.28; AEC Qualified: N; VDC_V: 75V; AEC Category: Q200; SizeAreaWB_mm2: 4.68
R73 = CMP-0023086-5: RES, 3.60 k, 1%, 0.1 W, 0603; Manufacturer: Yageo; Power_W: 100mW; TempCo: 100 ppm/C; Value_Code: 3k60; Value: 3.60k; Res_ohm: 3.6k; SizeX_mm: 1.6; SizeY_mm: 0.8; SizeZ_mm: 1; Value2: 0.1W; SizeArea_mm2: 1.28; AEC Qualified: N; VDC_V: 75V; AEC Category: Q200; SizeAreaWB_mm2: 4.68
R87 = CMP-0022808-4: RES, 150 k, 1%, 0.1 W, 0603; Manufacturer: Yageo; Power_W: 100mW; TempCo: 100 ppm/C; Value: 150k; EIA_Code: E96; SizeX_mm: 1.6; SizeY_mm: 0.8; SizeZ_mm: 1; Value2: 0.1W; SizeArea_mm2: 1.28; AEC Qualified: N; VDC_V: 75V; AEC Category: Q200; SizeAreaWB_mm2: 4.68
T1 = LLC Transformer: Transformer, 200 uH, PQ3230; Manufacturer: YAXIN ELECTRONICS; SymbolCreator: Altium; ValueDisplayed: 200µH; DCR_ohm: 2.5; Lp: 10; Ind_H: 0.0002; Rsec1_ohm: 0.4; Rsec2_ohm: 0.05; SizeX_mm: 22; SizeY_mm: 26.5; SizeZ_mm: 10.5
U2 = CMP-0088180-2: Switching Controllers LLC resonant controller with ultra-low power and ultra-quiet standby operation 14-SOIC -40 to 125; Manufacturer: Texas Instruments; CompType: IC; AEC Category: Q200; SizeZ_mm: 1.75mm; AEC Qualified: No
U3 U4 = CMP-0006173-3: Optocoupler, 5 kV, 80-160% CTR, TH; Manufacturer: Fairchild Semiconductor; CTR (Max): 160%; SizeAreaWB_mm2: 71.064; CTR (Min): 80%; SizeZ_mm: 5; SizeX_mm: 8.8; SizeY_mm: 4.58; SizeArea_mm2: 40.304; Voltage_Isolation_Vrms: 5kV
U5 = CMP-0084729-1: Programmable Shunt Regulator with Optimized Reference Current, DBZ0003A (SOT-23-3); Manufacturer: Texas Instruments; SizeY_mm: 3; SizeZ_mm: 1.12; SizeX_mm: 2.5; SizeAreaWB_mm2: 14; CompType: IC; AEC Qualified: N; AEC Category: Q200; SizeArea_mm2: 7.5
U6 = CMP-0075718-1: GENERAL-PURPOSE LOW-VOLTAGE COMPARATORS, D0008A (SOIC-8); Manufacturer: Texas Instruments; SizeAreaWB_mm2: 56.58; SizeArea_mm2: 30.38; SizeZ_mm: 1.75; SizeY_mm: 6.2; U/M: EA; CompType: IC; SizeX_mm: 4.9
U7 = CMP-0043697-1: Dual Operational Amplifier with Internal Reference, 3 to 32 V, -40 to 105 degC, 8-pin SOIC (D8), Green (RoHS & no Sb/Br); Manufacturer: Texas Instruments; Vio (25C)(Max)(mV): 4; GBW(Typ)(MHz): 0.9; CMRR(Min)(dB): 70; Total Supply Voltage(Max)(+5V is 5, +/-5V is 10): 32; Iq per channel(Max)(mA): 0.6; Total Supply Voltage(Min)(+5V is 5, +/-5V is 10): 3; Number of Channels: 2; Vn at 1kHz(Typ)(nV/rtHz): 50; Offset Drift(Typ)(uV/C): 7; Rating: Catalog; IIB(Max)(pA): 150000; Sub Family: General Purpose Amplifier, High Supply Voltage Amplifier (>=30V); Slew Rate(Typ)(V/us): 0.4
U8 = CMP-0013064-2: Low- and High-Side Measurement, Multichannel, Voltage Output, Current-Sense Amplifier, DBV0005A (SOT-5); Manufacturer: Texas Instruments; SizeX_mm: 2.8; SizeY_mm: 2.9; CompType: IC; SizeZ_mm: 1.45; SizeArea_mm2: 8.12; SizeAreaWB_mm2: 14.82; U/M: EA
